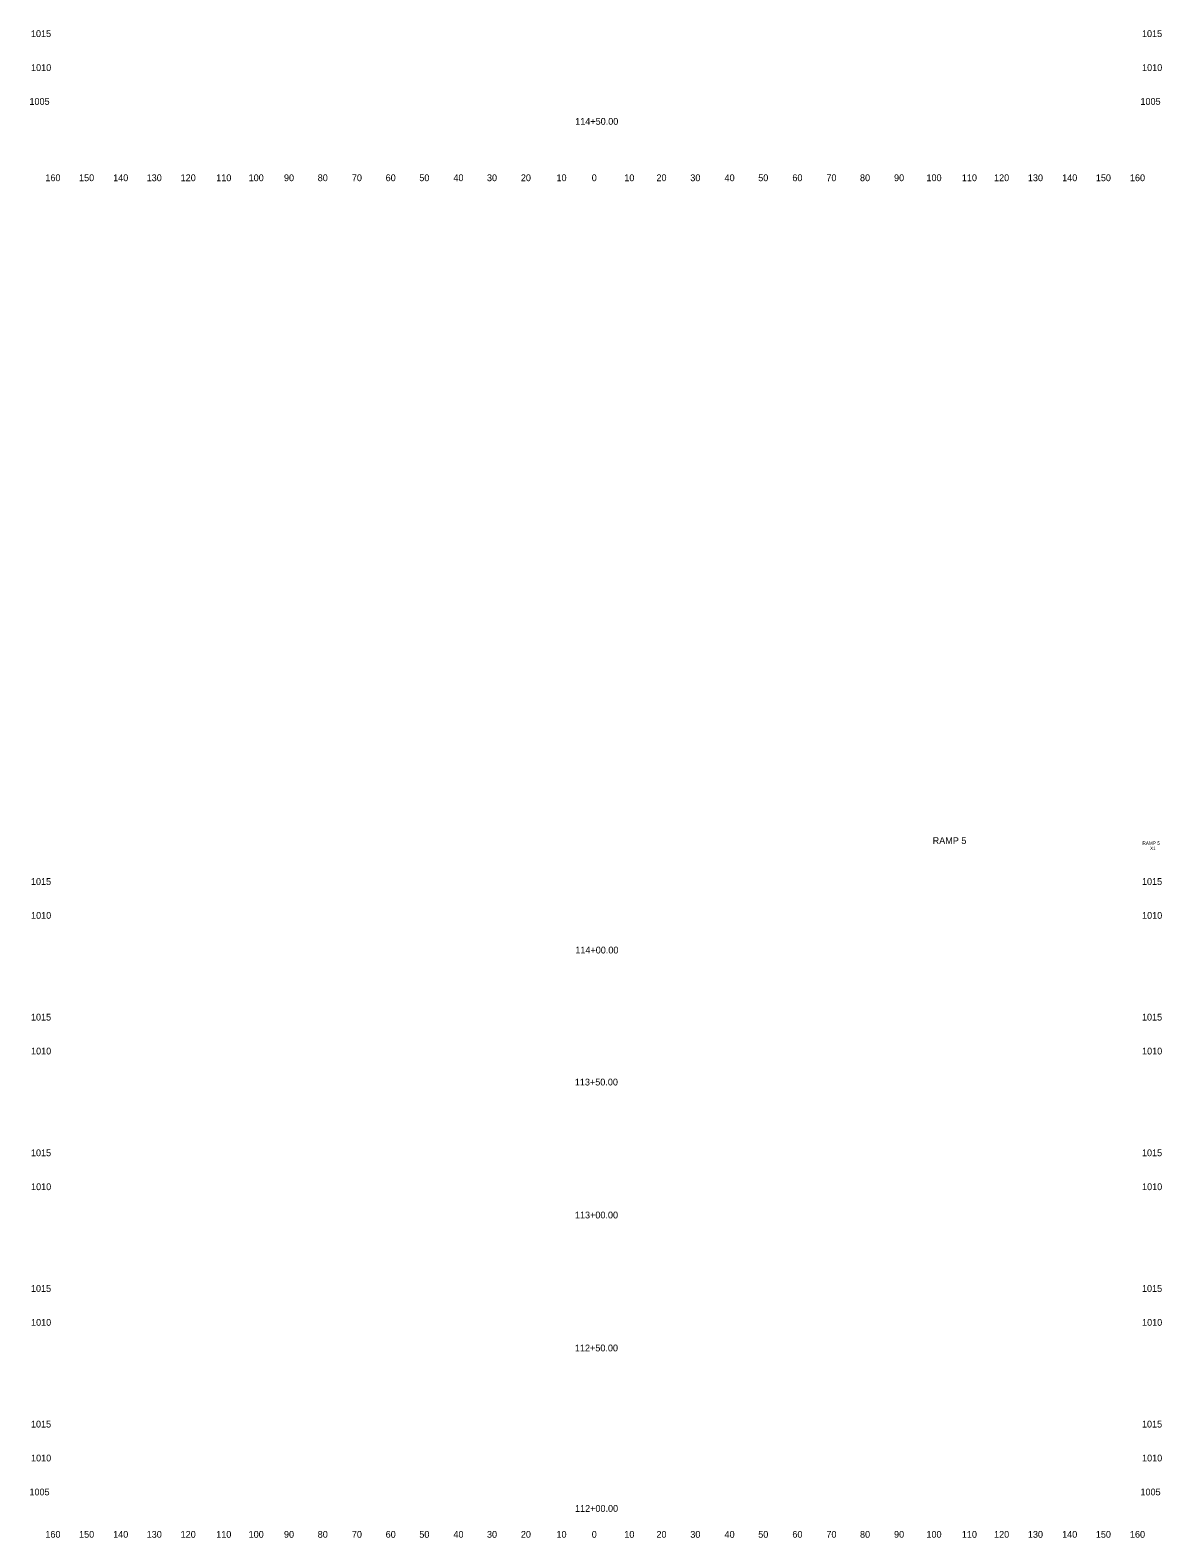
# Model space of a CAD drawing. Extents: x 4994 to 5842, y 4997 to 8804.
# Drawn here: x 4993.6 to 5327.5, y 4997.5 to 5442 of the extents above; entities that cross this region are included whole.
import ezdxf

# ---------------------------------------------------------------- set-up
doc = ezdxf.new("R2010")
doc.units = 0
for name, color, linetype in [('CLS_Search_Dist', 7, 'Continuous'), ('RD_XE_Ground', 7, 'Continuous'), ('UC_PD_Text', 7, 'Continuous')]:
    doc.layers.add(name, color=color, linetype=linetype)

msp = doc.modelspace()

# ---------------------------------------------------------------- texts
at = {"layer": 'CLS_Search_Dist'}
for s, p in [('1015', (4993.85, 5440)), ('1015', (5321.65, 5440)), ('1010', (4993.88, 5430)), ('1010', (5321.68, 5430)), ('1005', (4993.4, 5420)), ('1005', (5321.2, 5420)), ('160', (4998.1, 5397.5)), ('150', (5008.04, 5397.5)), ('140', (5018.1, 5397.5)), ('130', (5027.99, 5397.5)), ('120', (5038.01, 5397.5)), ('110', (5048.51, 5397.5)), ('100', (5058.07, 5397.5)), ('90', (5068.5, 5397.5)), ('80', (5078.46, 5397.5)), ('70', (5088.54, 5397.5)), ('60', (5098.5, 5397.5)), ('50', (5108.43, 5397.5)), ('40', (5118.5, 5397.5)), ('30', (5128.39, 5397.5)), ('20', (5138.4, 5397.5)), ('10', (5148.91, 5397.5)), ('0', (5159.3, 5397.5)), ('0', (5159.3, 5397.5)), ('10', (5168.91, 5397.5)), ('20', (5178.4, 5397.5)), ('30', (5188.39, 5397.5)), ('40', (5198.5, 5397.5)), ('50', (5208.43, 5397.5)), ('60', (5218.5, 5397.5)), ('70', (5228.54, 5397.5)), ('80', (5238.46, 5397.5)), ('90', (5248.5, 5397.5)), ('100', (5258.07, 5397.5)), ('110', (5268.51, 5397.5)), ('120', (5278.01, 5397.5)), ('130', (5287.99, 5397.5)), ('140', (5298.1, 5397.5)), ('150', (5308.04, 5397.5)), ('160', (5318.1, 5397.5)), ('1015', (4993.85, 5190)), ('1015', (5321.65, 5190)), ('1010', (4993.88, 5180)), ('1010', (5321.68, 5180)), ('1015', (4993.85, 5150)), ('1015', (5321.65, 5150)), ('1010', (4993.88, 5140)), ('1010', (5321.68, 5140)), ('1015', (4993.85, 5110)), ('1015', (5321.65, 5110)), ('1010', (4993.88, 5100)), ('1010', (5321.68, 5100)), ('1015', (4993.85, 5070)), ('1015', (5321.65, 5070)), ('1010', (4993.88, 5060)), ('1010', (5321.68, 5060)), ('1015', (4993.85, 5030)), ('1015', (5321.65, 5030)), ('1010', (4993.88, 5020)), ('1010', (5321.68, 5020)), ('1005', (4993.4, 5010)), ('1005', (5321.2, 5010)), ('160', (4998.1, 4997.5)), ('150', (5008.04, 4997.5)), ('140', (5018.1, 4997.5)), ('130', (5027.99, 4997.5)), ('120', (5038.01, 4997.5)), ('110', (5048.51, 4997.5)), ('100', (5058.07, 4997.5)), ('90', (5068.5, 4997.5)), ('80', (5078.46, 4997.5)), ('70', (5088.54, 4997.5)), ('60', (5098.5, 4997.5)), ('50', (5108.43, 4997.5)), ('40', (5118.5, 4997.5)), ('30', (5128.39, 4997.5)), ('20', (5138.4, 4997.5)), ('10', (5148.91, 4997.5)), ('0', (5159.3, 4997.5)), ('0', (5159.3, 4997.5)), ('10', (5168.91, 4997.5)), ('20', (5178.4, 4997.5)), ('30', (5188.39, 4997.5)), ('40', (5198.5, 4997.5)), ('50', (5208.43, 4997.5)), ('60', (5218.5, 4997.5)), ('70', (5228.54, 4997.5)), ('80', (5238.46, 4997.5)), ('90', (5248.5, 4997.5)), ('100', (5258.07, 4997.5)), ('110', (5268.51, 4997.5)), ('120', (5278.01, 4997.5)), ('130', (5287.99, 4997.5)), ('140', (5298.1, 4997.5)), ('150', (5308.04, 4997.5)), ('160', (5318.1, 4997.5))]:
    msp.add_text(s, height=2, dxfattribs=at).set_placement(p)
at = {"layer": 'RD_XE_Ground'}
for s, p in [('114+50.00', (5154.43, 5414.13)), ('114+00.00', (5154.46, 5169.78)), ('113+50.00', (5154.32, 5130.86)), ('113+00.00', (5154.35, 5091.66)), ('112+50.00', (5154.34, 5052.46)), ('112+00.00', (5154.37, 5005.13))]:
    msp.add_text(s, height=2, dxfattribs=at).set_placement(p)
at = {"layer": 'UC_PD_Text'}
for s, height, p in [('RAMP 5', 2, (5259.89, 5202.06)), ('RAMP 5', 1, (5321.78, 5201.8)), ('X1', 1, (5324.02, 5200.3))]:
    msp.add_text(s, height=height, dxfattribs=at).set_placement(p)

doc.saveas('drawing.dxf')
